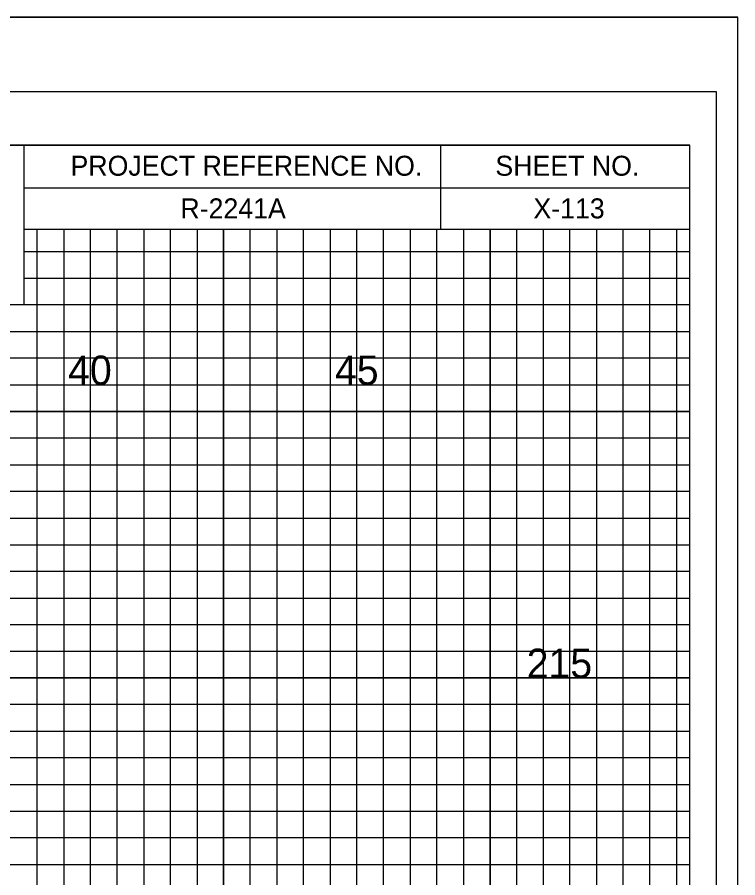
# Model space of a CAD drawing. Extents: x -4 to 103, y -2 to 492.
# Drawn here: x 89.88 to 103.4, y 192.9 to 209.05 of the extents above; entities that cross this region are included whole.
import ezdxf

# ---------------------------------------------------------------- set-up
doc = ezdxf.new("R2010")
doc.units = 0
for name, color, linetype in [('Exist XS Center Line Elevation Label', 7, 'Continuous'), ('Exist XS Ground Line', 7, 'Continuous'), ('Old_Level_10', 7, 'Continuous'), ('Old_Level_16', 7, 'Continuous'), ('Old_Level_3', 7, 'Continuous'), ('Old_Level_5', 7, 'Continuous'), ('Old_Level_8', 7, 'Continuous'), ('Prop Dimension', 7, 'Continuous'), ('Prop XS Finish Grade Earthwork', 7, 'Continuous'), ('Prop XS SE Text', 7, 'Continuous'), ('Prop XSC Text', 7, 'Continuous')]:
    doc.layers.add(name, color=color, linetype=linetype)

msp = doc.modelspace()

# ---------------------------------------------------------------- linework, layer by layer
at = {"layer": 'Old_Level_10'}
for p, q in [((91.25, 141.65), (91.25, 205.075)), ((93.75, 141.65), (93.75, 205.075)), ((96.25, 141.65), (96.25, 205.075)), ((98.75, 141.65), (98.75, 205.075)), ((101.25, 141.65), (101.25, 205.075)), ((90, 204.15), (102.5, 204.15)), ((0, 201.65), (102.5, 201.65)), ((0, 199.15), (102.5, 199.15)), ((0, 196.65), (102.5, 196.65)), ((0, 194.15), (102.5, 194.15))]:
    msp.add_line(p, q, dxfattribs=at)
at = {"layer": 'Old_Level_3'}
msp.add_line((-3.5, 209.05), (103.4, 209.05), dxfattribs=at)
at = {"layer": 'Old_Level_5'}
msp.add_lwpolyline([(103.4, 209.05), (-3.5, 209.05), (-3.5, 139.225), (103.4, 139.225)], close=True, dxfattribs=at)
at = {"layer": 'Old_Level_8'}
for points in [[(91.25, 141.65), (91.25, 205.075), (93.75, 205.075), (93.75, 141.65)], [(96.25, 141.65), (96.25, 205.075), (98.75, 205.075), (98.75, 141.65)], [(101.25, 141.65), (101.25, 205.075)], [(90, 204.15), (102.5, 204.15)], [(0, 199.15), (102.5, 199.15), (102.5, 201.65), (0, 201.65)], [(0, 194.15), (102.5, 194.15), (102.5, 196.65), (0, 196.65)]]:
    msp.add_lwpolyline(points, dxfattribs=at)
at = {"layer": 'Prop Dimension'}
for points in [[(90.25, 141.65), (90.25, 205.075), (90.75, 205.075), (90.75, 141.65)], [(91.75, 141.65), (91.75, 205.075), (92.25, 205.075), (92.25, 141.65)], [(92.75, 141.65), (92.75, 205.075), (93.25, 205.075), (93.25, 141.65)], [(94.25, 141.65), (94.25, 205.075), (94.75, 205.075), (94.75, 141.65)], [(95.25, 141.65), (95.25, 205.075), (95.75, 205.075), (95.75, 141.65)], [(96.75, 141.65), (96.75, 205.075), (97.25, 205.075), (97.25, 141.65)], [(97.75, 141.65), (97.75, 205.075), (98.25, 205.075), (98.25, 141.65)], [(99.25, 141.65), (99.25, 205.075), (99.75, 205.075), (99.75, 141.65)], [(100.25, 141.65), (100.25, 205.075)], [(100.25, 205.075), (100.75, 205.075), (100.75, 141.65), (101.75, 141.65), (101.75, 205.075), (102.25, 205.075), (102.25, 141.65)], [(102.5, 203.65), (102.5, 204.65), (90, 204.65)], [(0, 203.15), (102.5, 203.15), (102.5, 203.65), (0, 203.65)], [(0, 202.15), (102.5, 202.15), (102.5, 202.65), (0, 202.65)], [(0, 200.65), (102.5, 200.65), (102.5, 201.15), (0, 201.15)], [(0, 199.65), (102.5, 199.65), (102.5, 200.15), (0, 200.15)], [(0, 198.15), (102.5, 198.15), (102.5, 198.65), (0, 198.65)], [(0, 197.15), (102.5, 197.15), (102.5, 197.65), (0, 197.65)], [(0, 195.65), (102.5, 195.65), (102.5, 196.15), (0, 196.15)], [(0, 194.65), (102.5, 194.65), (102.5, 195.15), (0, 195.15)], [(0, 193.15), (102.5, 193.15), (102.5, 193.65), (0, 193.65)]]:
    msp.add_lwpolyline(points, dxfattribs=at)
at = {"layer": 'Prop XS SE Text'}
msp.add_lwpolyline([(103, 207.65), (-2.8, 207.65), (-2.8, 140.65), (103, 140.65)], close=True, dxfattribs=at)
at = {"layer": 'Prop XSC Text'}
for p, q in [((90, 206.65), (102.5, 206.65)), ((90, 206.65), (102.5, 206.65)), ((97.825, 205.075), (97.825, 206.65)), ((101.875, 206.65), (101.875, 206.65)), ((102.5, 206.65), (102.5, 206.65)), ((102.5, 205.075), (102.5, 206.65)), ((102.5, 206.65), (102.5, 206.65)), ((102.5, 206.65), (102.5, 206.65)), ((102.5, 205.075), (102.5, 206.65)), ((90, 205.85), (102.5, 205.85)), ((90, 205.075), (102.5, 205.075)), ((99.4, 205.075), (99.4, 205.075)), ((99.4, 205.075), (99.4, 205.075))]:
    msp.add_line(p, q, dxfattribs=at)
for points in [[(102.5, 206.65), (0, 206.65), (0, 141.65), (102.5, 141.65)], [(83.75, 206.65), (90, 206.65), (90, 203.65), (83.75, 203.65)]]:
    msp.add_lwpolyline(points, close=True, dxfattribs=at)

# ---------------------------------------------------------------- texts
at = {"layer": 'Exist XS Center Line Elevation Label'}
msp.add_text('R-2241A', height=0.375, dxfattribs=at).set_placement((92.9378, 205.275))
at = {"layer": 'Exist XS Ground Line'}
msp.add_text('X-113', height=0.375, dxfattribs=at).set_placement((99.5637, 205.275))
at = {"layer": 'Old_Level_16'}
for s, p in [('40', (90.8313, 202.15)), ('45', (95.8399, 202.15))]:
    msp.add_text(s, height=0.55, dxfattribs=at).set_placement(p)
at = {"layer": 'Prop XS Finish Grade Earthwork'}
msp.add_text('215', height=0.55, dxfattribs=at).set_placement((99.4383, 196.65))
at = {"layer": 'Prop XSC Text'}
for s, p in [('PROJECT REFERENCE NO.', (90.875, 206.075)), ('SHEET NO.', (98.85, 206.075))]:
    msp.add_text(s, height=0.375, dxfattribs=at).set_placement(p)

doc.saveas('drawing.dxf')
